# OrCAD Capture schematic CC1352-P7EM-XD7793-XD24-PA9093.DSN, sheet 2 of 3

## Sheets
2 CC1352-P7EM-XD7793-XD24-PA9093: size A3
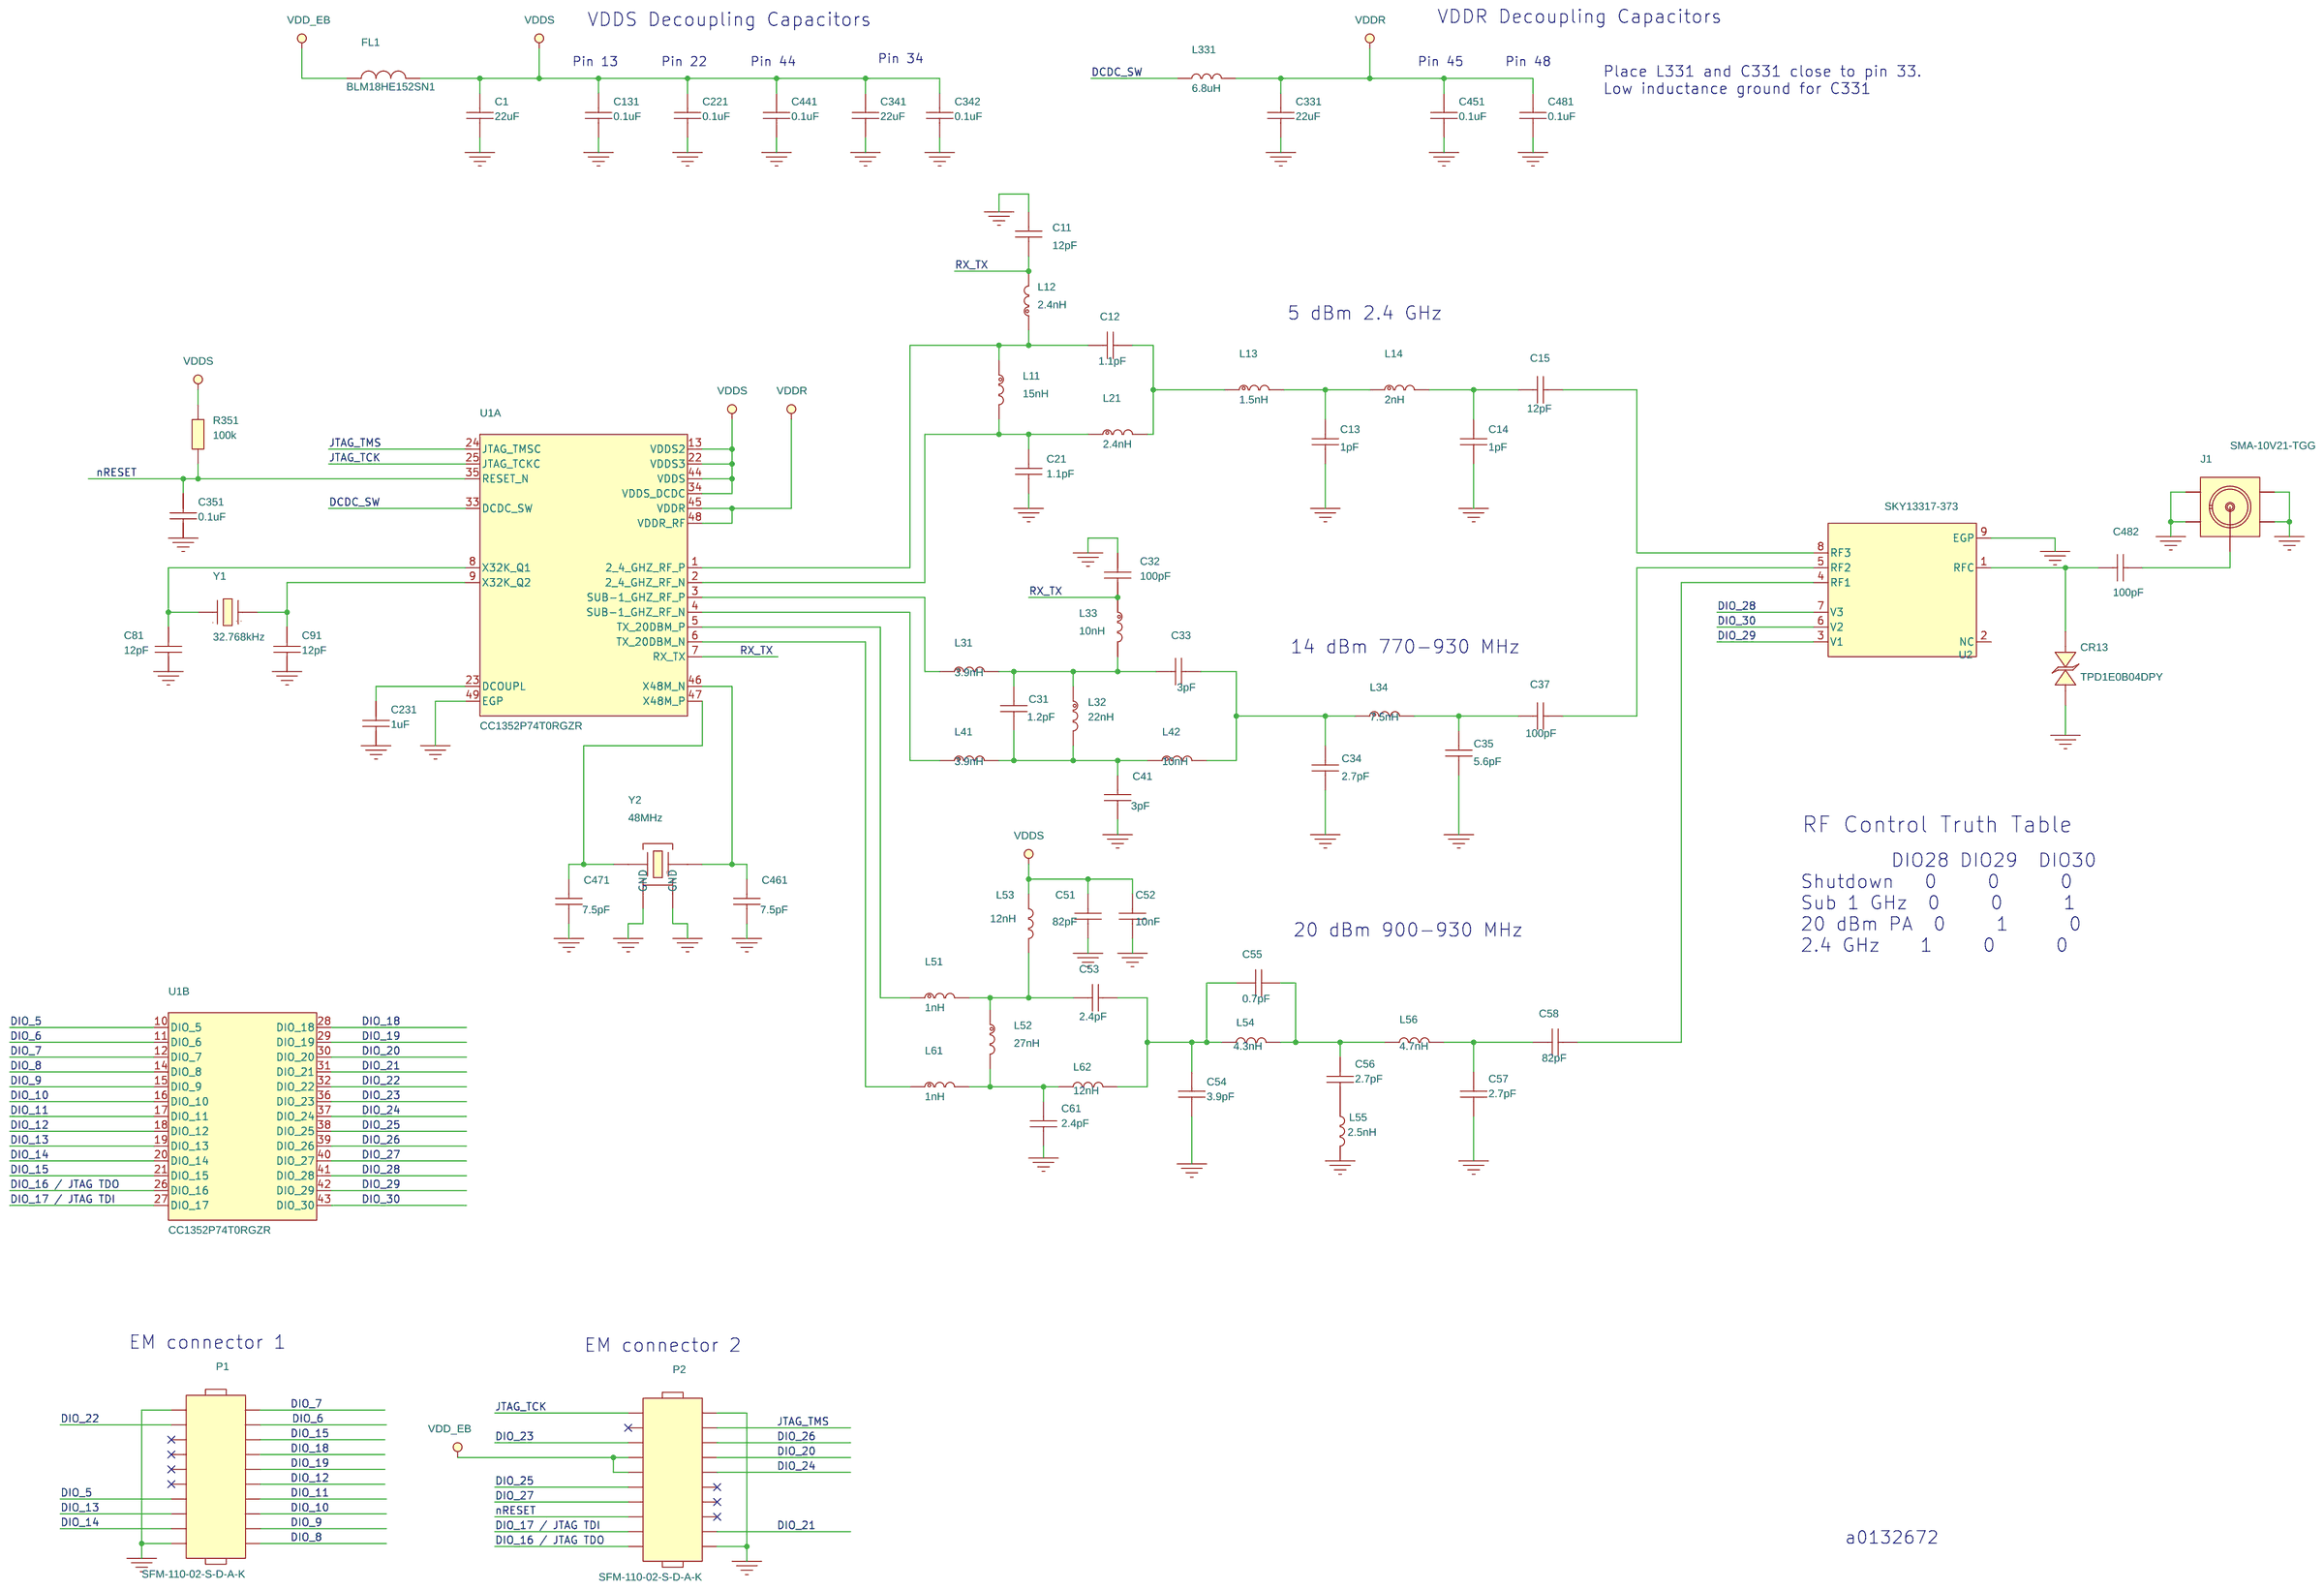
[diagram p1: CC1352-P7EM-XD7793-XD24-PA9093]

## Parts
C1  22uF  [CAPC1608X100A2N]
C11  12pF  [CAPC1005X60B2N]
C12  1.1pF  [CAPC1005X60B2N]
C13  1pF  [CAPC1005X60B2N]
C14  1pF  [CAPC1005X60B2N]
C15  12pF  [CAPC1005X60B2N]
C21  1.1pF  [CAPC1005X60B2N]
C31  1.2pF  [CAPC1005X60B2N]
C32  100pF  [CAPC1005X60B2N]
C33  3pF  [CAPC1005X60B2N]
C34  2.7pF  [CAPC1005X60B2N]
C35  5.6pF  [CAPC1005X60B2N]
C37  100pF  [CAPC1005X60B2N]
C41  3pF  [CAPC1005X60B2N]
C51  82pF  [CAPC1005X60B2N]
C52  10nF  [CAPC1005X60B2N]
C53  2.4pF  [CAPC1005X60B2N]
C54  3.9pF  [CAPC1005X60B2N]
C55  0.7pF  [CAPC1005X60B2N]
C56  2.7pF  [CAPC1005X60B2N]
C57  2.7pF  [CAPC1005X60B2N]
C58  82pF  [CAPC1005X60B2N]
C61  2.4pF  [CAPC1005X60B2N]
C81  12pF  [CAPC1005X60B2N]
C91  12pF  [CAPC1005X60B2N]
C131  0.1uF  [CAPC1005X60B2N]
C221  0.1uF  [CAPC1005X60B2N]
C231  1uF  [CAPC1005X60B2N]
C331  22uF  [CAPC1608X100A2N]
C341  22uF  [CAPC1608X100A2N]
C342  0.1uF  [CAPC1005X60B2N]
C351  0.1uF  [CAPC1005X60B2N]
C441  0.1uF  [CAPC1005X60B2N]
C451  0.1uF  [CAPC1005X60B2N]
C461  7.5pF  [CAPC1005X60B2N]
C471  7.5pF  [CAPC1005X60B2N]
C481  0.1uF  [CAPC1005X60B2N]
C482  100pF  [CAPC1005X60B2N]
CR13  TPD1E0B04DPY  [SON65P100X60X45-2A2N]
FL1  BLM18HE152SN1  [FIL_BLM18HE152SN1DN]
J1  SMA-10V21-TGG  [HUSTSAN_SMA10V21TGGAN]
L11  15nH  [INDC1005X60D2N]
L12  2.4nH  [INDC1005X60D2N]
L13  1.5nH  [INDC1005X60D2N]
L14  2nH  [INDC1005X60D2N]
L21  2.4nH  [INDC1005X60D2N]
L31  3.9nH  [INDC1005X60D2N]
L32  22nH  [INDC1005X60D2N]
L33  10nH  [INDC1005X60D2N]
L34  7.5nH  [INDC1005X60D2N]
L41  3.9nH  [INDC1005X60D2N]
L42  10nH  [INDC1005X60D2N]
L51  1nH  [INDC1005X60D2N]
L52  27nH  [INDC1005X60D2N]
L53  12nH  [INDC1005X60B2N]
L54  4.3nH  [INDC1005X60B2N]
L55  2.5nH  [INDC1005X60B2N]
L56  4.7nH  [INDC1005X60B2N]
L61  1nH  [INDC1005X60D2N]
L62  12nH  [INDC1005X60B2N]
L331  6.8uH  [INDC2012X150A2N]
P1  SFM-110-02-S-D-A-K  [SAMTEC_SFM11002AN]
P2  SFM-110-02-S-D-A-K  [SAMTEC_SFM11002AN]
R351  100k  [RESC1005X40B2N]
U1  CC1352P74T0RGZR  [QFNFC50P700X700X100-49A2N]  (sections A,B)
U2  SKY13317-373  [SON40P150X150X50-9A2N]
Y1  32.768kHz  [XTAL_TZ1166C_A2N]
Y2  48MHz  [OSCCC200X160X50-4A2N]

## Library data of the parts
C1 C331 C341 = CAPACITOR: CAPACITOR, CERAMIC X6S, 22uF, 6.3V, -20%/+20%, -55DEGC/+105DEGC, 0603, SMD; ALT_SYMBOLS: CAPC1608X100A2L,CAPC1608X100A2M; Additional Datasheet URL: https://search.murata.co.jp/Ceramy/image/img/A01X/G101/ENG/GRM188C80J226ME15-02A.pdf; AutoDoc File: https://notefied-dynamic-precision.com/DB/Apps/Desktop/Item/Object.aspx?id=104385; BU Name: DYNAMIC PRECISION GDANSK; Budget Currency: EUR; Budget Price: 0.062; Budgetary Price: 0.07648 USD; Client Status: UNDER_REVIEW; Datasheet URL: https://www.murata.com/-/media/webrenewal/support/library/catalog/products/capacitor/mlcc/c02e.ashx; Datasheet URL 1: http://psearch.murata.com/capacitor/product/GRM188R60J226MEA0%23.pdf; Datasheet URL 2: http://search.murata.co.jp/Ceramy/image/img/w_hinm/L0005E.pdf; Definied Quality: INDUSTRIAL; Dielectric Type: X6S; Esd Level: N/A; Lead Time: 15; LifeCycle Status: ACTIVE; MPN: GRM188R60J226MEA0D; MPN Status: ACTIVE; Manufacturer: MURATA; Mass: 0.0091g; Max Oper Temp: +85DEGC; Max Tol: +20%; Maximum Operating Temperature: +105DEGC; Maximum Tolerance: +20%; Min Oper Temp: -55DEGC; Min Tol: -20%; Minimum Operating Temperature: -55DEGC; Minimum Tolerance: -20%; Mounting Type: SMD; NOTE Status: PREFERRED; NOTEfied URL: https://notefied-dynamic-precision.com/NOTEfiedWebInterface/part/show?partNumber=02-09737; PCB Package: 0603; Packing Size: 4000; Packing Type: Tape & Reel; Part Number: 02-09737; Part Type: Capacitor|CERAMIC|0603|STANDARD; REACH/SVHC Compliance: Compliant; REACH/SVHC Details: SVHC List Version Jan 16, 2020; REACH/SVHC Source: REACH Declaration; REACH/SVHC Status: Unaffected; REACH/SVHC_COMPLIANCE: COMPLIANT; REACH/SVHC_DETAILS: SVHC LIST VERSION Dec 17, 2015; REACH/SVHC_SOURCE: REACH DECLARATION; REACH/SVHC_STATUS: UNAFFECTED; ROHS: Compliant; Rated Current: N/A; Rated Voltage: 6.3V; Revision: R001; RoHS Status: ROHS_COMPLIANT; Rtd Voltage: 6.3V; Status: Released; Texas Part Status: Under Review; Type: Capacitor; Vendor: MURATA; Vendor Part Number: GRM188C80J226ME15D; Vendor Part Status: Active; WEIGHT: 0.0091g
C11 C15 = CAPACITOR: CAPACITOR, CERAMIC C0G/NP0, 12pF, 50V, -5%/+5%, -55DEGC/+125DEGC, 0402, SMD; Additional Datasheet URL: https://search.murata.co.jp/Ceramy/image/img/A01X/G101/ENG/GJM1555C1H120JB01-01.pdf; AutoDoc File: https://notefied-dynamic-precision.com/DB/Apps/Desktop/Item/Object.aspx?id=113345; BU Name: TEXAS INSTRUMENTS NORWAY; Budget Currency: EUR; Budget Price: 0.007; Datasheet URL: https://www.murata.com/-/media/webrenewal/support/library/catalog/products/capacitor/mlcc/c02e.ashx; Datasheet URL 1: http://psearch.murata.com/capacitor/product/GRM1555C1H120JA01%23.pdf; Datasheet URL 2: http://search.murata.co.jp/Ceramy/image/img/w_hinm/L0005E.pdf; Dielectric Type: C0G/NP0; Mass: 0.0016g; Max Oper Temp: +125DEGC; Max Tol: +5%; Maximum Operating Temperature: +125DEGC; Maximum Tolerance: +5%; Min Oper Temp: -55DEGC; Min Tol: -5%; Minimum Operating Temperature: -55DEGC; Minimum Tolerance: -5%; Mounting Type: SMD; NOTEfied URL: https://notefied-dynamic-precision.com/NOTEfiedWebInterface/part/show?partNumber=02-09704; PCB Package: 0402; Packing Size: 10000; Packing Type: Tape & Reel; Part Number: 02-09704; Part Type: Capacitor|CERAMIC|0402|STANDARD; REACH/SVHC Compliance: Compliant; REACH/SVHC Details: SVHC List Version Jan 16, 2020; REACH/SVHC Source: REACH Declaration; REACH/SVHC Status: Unaffected; REACH/SVHC_COMPLIANCE: COMPLIANT; REACH/SVHC_DETAILS: SVHC LIST VERSION Dec 17, 2015; REACH/SVHC_SOURCE: REACH DECLARATION; REACH/SVHC_STATUS: UNAFFECTED; ROHS: Compliant; Rated Voltage: 50V; Revision: R002; RoHS Status: ROHS_COMPLIANT; Rtd Voltage: 50V; Status: Released; Texas Part Status: Under Review; Type: Capacitor; Vendor: MURATA; Vendor Part Number: GJM1555C1H120JB01D; Vendor Part Status: Active; Weight: 0.0016g
C12 C21 = CAPACITOR: CAPACITOR, CERAMIC C0G/NP0, 1.1pF, 50V, -0.1pF/+0.1pF, -55DEGC/+125DEGC, 0402, SMD; Additional Datasheet URL: https://search.murata.co.jp/Ceramy/image/img/A01X/G101/ENG/GJM1555C1H1R1BB01-01.pdf; AutoDoc File: https://notefied-dynamic-precision.com/DB/Apps/Desktop/Item/Object.aspx?id=116030; BU Name: TEXAS INSTRUMENTS NORWAY; Budget Currency: EUR; Budget Price: 0.011; Client Status: UNDER_REVIEW; Datasheet URL: https://www.murata.com/-/media/webrenewal/support/library/catalog/products/capacitor/mlcc/c02e.ashx; Datasheet URL 1: http://psearch.murata.com/capacitor/product/GRM1555C1H1R1BA01%23.pdf; Datasheet URL 2: http://search.murata.co.jp/Ceramy/image/img/w_hinm/L0005E.pdf; Dielectric Type: C0G/NP0; Mass: 0.0016g; Max Oper Temp: +125DEGC; Max Tol: +0.1pF; Maximum Operating Temperature: +125DEGC; Maximum Tolerance: +0.1pF; Min Oper Temp: -55DEGC; Min Tol: -0.1pF; Minimum Operating Temperature: -55DEGC; Minimum Tolerance: -0.1pF; Mounting Type: SMD; NOTEfied URL: https://notefied-dynamic-precision.com/NOTEfiedWebInterface/part/show?partNumber=02-09708; PCB Package: 0402; Packing Size: 10000; Packing Type: Tape & Reel; Part Number: 02-09708; Part Type: Capacitor|CERAMIC|0402|STANDARD; REACH/SVHC Compliance: Compliant; REACH/SVHC Details: SVHC List Version Jan 16, 2020; REACH/SVHC Source: REACH Declaration; REACH/SVHC Status: Unaffected; REACH/SVHC_COMPLIANCE: COMPLIANT; REACH/SVHC_DETAILS: SVHC LIST VERSION Jun 20, 2016; REACH/SVHC_SOURCE: REACH DECLARATION; REACH/SVHC_STATUS: UNAFFECTED; ROHS: Compliant; Rated Voltage: 50V; Revision: R002; RoHS Status: ROHS_COMPLIANT; Rtd Voltage: 50V; Status: Released; Texas Part Status: Under Review; Type: Capacitor; Vendor: MURATA; Vendor Part Number: GJM1555C1H1R1BB01D; Vendor Part Status: Active; Weight: 0.0016g
C13 C14 = CAPACITOR: CAPACITOR, CERAMIC C0G/NP0, 1pF, 50V, -0.1pF/+0.1pF, -55DEGC/+125DEGC, 0402, SMD; Additional Datasheet URL: https://search.murata.co.jp/Ceramy/image/img/A01X/G101/ENG/GJM1555C1H1R0BB01-01.pdf; AutoDoc File: https://notefied-dynamic-precision.com/DB/Apps/Desktop/Item/Object.aspx?id=116031; BU Name: TEXAS INSTRUMENTS NORWAY; Budget Currency: EUR; Budget Price: 0.011; Client Status: UNDER_REVIEW; Datasheet URL: https://www.murata.com/-/media/webrenewal/support/library/catalog/products/capacitor/mlcc/c02e.ashx; Datasheet URL 1: http://psearch.murata.com/capacitor/product/GRM1555C1H1R0BA01%23.pdf; Datasheet URL 2: http://search.murata.co.jp/Ceramy/image/img/w_hinm/L0005E.pdf; Dielectric Type: C0G/NP0; Mass: 0.0016g; Max Oper Temp: +125DEGC; Max Tol: +0.1pF; Maximum Operating Temperature: +125DEGC; Maximum Tolerance: +0.1pF; Min Oper Temp: -55DEGC; Min Tol: -0.1pF; Minimum Operating Temperature: -55DEGC; Minimum Tolerance: -0.1pF; Mounting Type: SMD; NOTEfied URL: https://notefied-dynamic-precision.com/NOTEfiedWebInterface/part/show?partNumber=02-09705; PCB Package: 0402; Packing Size: 10000; Packing Type: Tape & Reel; Part Number: 02-09705; Part Type: Capacitor|CERAMIC|0402|STANDARD; REACH/SVHC Compliance: Compliant; REACH/SVHC Details: SVHC List Version Jan 16, 2020; REACH/SVHC Source: REACH Declaration; REACH/SVHC Status: Unaffected; REACH/SVHC_COMPLIANCE: COMPLIANT; REACH/SVHC_DETAILS: SVHC LIST VERSION Dec 17, 2015; REACH/SVHC_SOURCE: REACH DECLARATION; REACH/SVHC_STATUS: UNAFFECTED; ROHS: Compliant; Rated Voltage: 50V; Revision: R002; RoHS Status: ROHS_COMPLIANT; Rtd Voltage: 50V; Status: Released; Texas Part Status: Under Review; Type: Capacitor; Vendor: MURATA; Vendor Part Number: GJM1555C1H1R0BB01D; Vendor Part Status: Active; Weight: 0.0016g
C31 = CAPACITOR: CAPACITOR, CERAMIC C0G/NP0, 1.2pF, 50V, -0.1pF/+0.1pF, -55DEGC/+125DEGC, 0402, SMD; Additional Datasheet URL: https://search.murata.co.jp/Ceramy/image/img/A01X/G101/ENG/GJM1555C1H1R2BB01-01.pdf; Datasheet URL: https://www.murata.com/-/media/webrenewal/support/library/catalog/products/capacitor/mlcc/c02e.ashx; Dielectric Type: C0G/NP0; Mass: 0.0016g; Maximum Operating Temperature: +125DEGC; Maximum Tolerance: +0.1pF; Minimum Operating Temperature: -55DEGC; Minimum Tolerance: -0.1pF; Mounting Type: SMD; NOTEfied URL: https://notefied-dynamic-precision.com/NOTEfiedWebInterface/part/show?partNumber=02-09709; PCB Package: 0402; Packing Size: 10000; Packing Type: Tape & Reel; Part Number: 02-09709; Part Type: Capacitor|CERAMIC|0402|STANDARD; REACH/SVHC Compliance: Compliant; REACH/SVHC Details: SVHC List Version Jan 16, 2020; REACH/SVHC Source: REACH Declaration; REACH/SVHC Status: Unaffected; ROHS: Compliant; Rated Voltage: 50V; Revision: R002; Status: Released; Texas Part Status: Under Review; Type: Capacitor; Vendor: MURATA; Vendor Part Number: GJM1555C1H1R2BB01D; Vendor Part Status: Active
C32 C37 = CAPACITOR: CAPACITOR, CERAMIC C0G/NP0, 100pF, 50V, -5%/+5%, -55DEGC/+125DEGC, 0402, SMD; Additional Datasheet URL: https://search.murata.co.jp/Ceramy/image/img/A01X/G101/ENG/GRT1555C1H101JA02-01.pdf; AutoDoc File: https://notefied-dynamic-precision.com/DB/Apps/Desktop/Item/Object.aspx?id=113347; BU Name: TEXAS INSTRUMENTS NORWAY; Budget Currency: EUR; Budget Price: 0.004; Budgetary Price: 0.023 EUR; Datasheet URL: https://www.murata.com/-/media/webrenewal/support/library/catalog/products/capacitor/mlcc/c02e.ashx?la=en-gb; Datasheet URL 1: http://psearch.murata.com/capacitor/product/GRM1555C1H101JA01%23.pdf; Datasheet URL 2: http://search.murata.co.jp/Ceramy/image/img/w_hinm/L0005E.pdf; Definied Quality: INDUSTRIAL; Dielectric Type: C0G/NP0; Esd Level: N/A; Lead Time: 19; MPN: GRM1555C1H101JA01D; MPN Status: ACTIVE; MSL: 1; MTBF: N/A; MTBF Standard: N/A; Manufacturer: MURATA; Mass: 0.0016g; Max Oper Temp: +125DEGC; Max Tol: +5%; Maximum Operating Temperature: +125DEGC; Maximum Tolerance: +5%; Min Oper Temp: -55DEGC; Min Tol: -5%; Minimum Operating Temperature: -55DEGC; Minimum Tolerance: -5%; Mounting Type: SMD; NOTE Status: PREFERRED; NOTEfied URL: https://notefied-dynamic-precision.com/NOTEfiedWebInterface/part/show?partNumber=02-09727; Old Footprint: CAPC1005X60N; PCB Package: 0402; Packing Size: 10000; Packing Type: Tape & Reel; Part Number: 02-09727; Part Type: Capacitor|CERAMIC|0402|STANDARD; REACH/SVHC Compliance: Compliant; REACH/SVHC Details: SVHC List Version Jan 16, 2020; REACH/SVHC Source: REACH Declaration; REACH/SVHC Status: Unaffected; REACH/SVHC_COMPLIANCE: COMPLIANT; REACH/SVHC_DETAILS: SVHC LIST VERSION Dec 17, 2015; REACH/SVHC_SOURCE: REACH DECLARATION; REACH/SVHC_STATUS: UNAFFECTED; ROHS: Compliant; Rated Voltage: 50V; Revision: R002; RoHS Status: ROHS_COMPLIANT; Rtd Voltage: 50V; Status: Released; Texas Part Status: Under Review; Type: Capacitor; Vendor: MURATA; Vendor Part Number: GRT1555C1H101JA02D; Vendor Part Status: Active; WEIGHT: 0.0016g
C33 C41 = CAPACITOR: CAPACITOR, CERAMIC C0G/NP0, 3pF, 50V, -0.25pF/+0.25pF, -55DEGC/+125DEGC, 0402, SMD; Additional Datasheet URL: https://search.murata.co.jp/Ceramy/image/img/A01X/G101/ENG/GJM1555C1H3R0CB01-01.pdf; Datasheet URL: https://www.murata.com/-/media/webrenewal/support/library/catalog/products/capacitor/mlcc/c02e.ashx; Dielectric Type: C0G/NP0; Mass: 0.0016g; Maximum Operating Temperature: +125DEGC; Maximum Tolerance: +0.25pF; Minimum Operating Temperature: -55DEGC; Minimum Tolerance: -0.25pF; Mounting Type: SMD; NOTEfied URL: https://notefied-dynamic-precision.com/NOTEfiedWebInterface/part/show?partNumber=02-09713; PCB Package: 0402; Packing Size: 10000; Packing Type: Tape & Reel; Part Number: 02-09713; Part Type: Capacitor|CERAMIC|0402|STANDARD; REACH/SVHC Compliance: Compliant; REACH/SVHC Details: SVHC List Version Jan 16, 2020; REACH/SVHC Source: REACH Declaration; REACH/SVHC Status: Unaffected; ROHS: Compliant; Rated Voltage: 50V; Revision: R002; Status: Released; Texas Part Status: Under Review; Type: Capacitor; Vendor: MURATA; Vendor Part Number: GJM1555C1H3R0CB01D; Vendor Part Status: Active
C34 = CAPACITOR: CAPACITOR, CERAMIC C0G/NP0, 2.7pF, 50V, -0.25pF/+0.25pF, -55DEGC/+125DEGC, 0402, SMD; Additional Datasheet URL: https://search.murata.co.jp/Ceramy/image/img/A01X/G101/ENG/GJM1555C1H2R7CB01-01.pdf; Datasheet URL: https://www.murata.com/-/media/webrenewal/support/library/catalog/products/capacitor/mlcc/c02e.ashx; Dielectric Type: C0G/NP0; Mass: 0.0016g; Maximum Operating Temperature: +125DEGC; Maximum Tolerance: +0.25pF; Minimum Operating Temperature: -55DEGC; Minimum Tolerance: -0.25pF; Mounting Type: SMD; NOTEfied URL: https://notefied-dynamic-precision.com/NOTEfiedWebInterface/part/show?partNumber=02-09712; PCB Package: 0402; Packing Size: 10000; Packing Type: Tape & Reel; Part Number: 02-09712; Part Type: Capacitor|CERAMIC|0402|STANDARD; REACH/SVHC Compliance: Compliant; REACH/SVHC Details: SVHC List Version Jan 16, 2020; REACH/SVHC Source: REACH Declaration; REACH/SVHC Status: Unaffected; ROHS: Compliant; Rated Voltage: 50V; Revision: R002; Status: Released; Texas Part Status: Under Review; Type: Capacitor; Vendor: MURATA; Vendor Part Number: GJM1555C1H2R7CB01D; Vendor Part Status: Active
C35 = CAPACITOR: CAPACITOR, CERAMIC C0G/NP0, 5.6pF, 50V, -0.25pF/+0.25pF, -55DEGC/+125DEGC, 0402, SMD; Additional Datasheet URL: https://search.murata.co.jp/Ceramy/image/img/A01X/G101/ENG/GJM1555C1H5R6CB01-01.pdf; Datasheet URL: https://www.murata.com/-/media/webrenewal/support/library/catalog/products/capacitor/mlcc/c02e.ashx; Dielectric Type: C0G/NP0; Mass: 0.0016g; Maximum Operating Temperature: +125DEGC; Maximum Tolerance: +0.25pF; Minimum Operating Temperature: -55DEGC; Minimum Tolerance: -0.25pF; Mounting Type: SMD; NOTEfied URL: https://notefied-dynamic-precision.com/NOTEfiedWebInterface/part/show?partNumber=02-09716; PCB Package: 0402; Packing Size: 10000; Packing Type: Tape & Reel; Part Number: 02-09716; Part Type: Capacitor|CERAMIC|0402|STANDARD; REACH/SVHC Compliance: Compliant; REACH/SVHC Details: SVHC List Version Jan 16, 2020; REACH/SVHC Source: REACH Declaration; REACH/SVHC Status: Unaffected; ROHS: Compliant; Rated Voltage: 50V; Revision: R002; Status: Released; Texas Part Status: Under Review; Type: Capacitor; Vendor: MURATA; Vendor Part Number: GJM1555C1H5R6CB01D; Vendor Part Status: Active
C51 C58 = CAPACITOR: CAPACITOR, CERAMIC C0G/NP0, 82pF, 50V, -5%/+5%, -55DEGC/+125DEGC, 0402, SMD; Additional Datasheet URL: https://search.murata.co.jp/Ceramy/image/img/A01X/G101/ENG/GRT1555C1H820JA02-01.pdf; AutoDoc File: https://notefied-dynamic-precision.com/DB/Apps/Desktop/Item/Object.aspx?id=115925; BU Name: TEXAS INSTRUMENTS NORWAY; Budget Currency: EUR; Budget Price: 0.007; Budgetary Price: 0.008 EUR; Client Status: UNDER_REVIEW; Country of Origin: Missing Info; Datasheet URL: https://www.murata.com/-/media/webrenewal/support/library/catalog/products/capacitor/mlcc/c02e.ashx?la=en-gb; Datasheet URL 1: http://psearch.murata.com/capacitor/product/GRM1555C1H820JA01%23.pdf; Datasheet URL 2: http://search.murata.co.jp/Ceramy/image/img/w_hinm/L0005E.pdf; Dielectric Type: C0G/NP0; Lead Time: 19; Mass: 0.0016g; Max Oper Temp: +125DEGC; Max Tol: +5%; Maximum Operating Temperature: +125DEGC; Maximum Tolerance: +5%; Min Oper Temp: -55DEGC; Min Tol: -5%; Minimum Operating Temperature: -55DEGC; Minimum Tolerance: -5%; Mounting Type: SMD; NOTEfied URL: https://notefied-dynamic-precision.com/NOTEfiedWebInterface/part/show?partNumber=02-09729; PCB Package: 0402; Packing Size: 10000; Packing Type: Tape & Reel; Part Number: 02-09729; Part Type: Capacitor|CERAMIC|0402|STANDARD; REACH/SVHC Compliance: Compliant; REACH/SVHC Details: SVHC List Version Jan 16, 2020; REACH/SVHC Source: REACH Declaration; REACH/SVHC Status: Unaffected; REACH/SVHC_COMPLIANCE: COMPLIANT; REACH/SVHC_DETAILS: SVHC LIST VERSION Jun 20, 2016; REACH/SVHC_SOURCE: REACH DECLARATION; REACH/SVHC_STATUS: UNAFFECTED; ROHS: Compliant; Rated Voltage: 50V; Revision: R002; RoHS Status: ROHS_COMPLIANT; Rtd Voltage: 50V; Status: Released; Texas Part Status: Under Review; Type: Capacitor; Vendor: MURATA; Vendor Part Number: GRT1555C1H820JA02D; Vendor Part Status: Active; Weight: 0.0016g
C52 = CAPACITOR: CAPACITOR, CERAMIC X7R, 10nF, 50V, -20%/+20%, -55DEGC/+125DEGC, 0402, SMD; Additional Datasheet URL: https://search.murata.co.jp/Ceramy/image/img/A01X/G101/ENG/GRM155R71H103MA88-01A.pdf; AutoDoc File: https://notefied-dynamic-precision.com/DB/Apps/Desktop/Item/Object.aspx?id=114570; BU Name: TEXAS INSTRUMENTS NORWAY; Budget Currency: EUR; Budget Price: 0.003; Client Status: UNDER_REVIEW; Datasheet URL: https://www.murata.com/-/media/webrenewal/support/library/catalog/products/capacitor/mlcc/c02e.ashx; Datasheet URL 1: http://psearch.murata.com/capacitor/product/GRM155R71E103KA01%23.pdf; Datasheet URL 2: http://search.murata.co.jp/Ceramy/image/img/w_hinm/L0005E.pdf; Dielectric Type: X7R; Mass: 0.0016g; Max Oper Temp: +125DEGC; Max Tol: +10%; Maximum Operating Temperature: +125DEGC; Maximum Tolerance: +20%; Min Oper Temp: -55DEGC; Min Tol: -10%; Minimum Operating Temperature: -55DEGC; Minimum Tolerance: -20%; Mounting Type: SMD; NOTEfied URL: https://notefied-dynamic-precision.com/NOTEfiedWebInterface/part/show?partNumber=02-09722; PCB Package: 0402; Packing Size: 10000; Packing Type: Tape & Reel; Part Number: 02-09722; Part Type: Capacitor|CERAMIC|0402|STANDARD; REACH/SVHC Compliance: Compliant; REACH/SVHC Details: SVHC List Version Jan 16, 2020; REACH/SVHC Source: REACH Declaration; REACH/SVHC Status: Unaffected; REACH/SVHC_COMPLIANCE: COMPLIANT; REACH/SVHC_DETAILS: SVHC LIST VERSION Jun 20, 2016; REACH/SVHC_SOURCE: REACH DECLARATION; REACH/SVHC_STATUS: UNAFFECTED; ROHS: Compliant; Rated Voltage: 50V; Revision: R002; RoHS Status: ROHS_COMPLIANT; Rtd Voltage: 25V; Status: Released; Texas Part Status: Under Review; Type: Capacitor; Vendor: MURATA; Vendor Part Number: GRM155R71H103MA88D; Vendor Part Status: Active; Weight: 0.0016g
C53 C61 = CAPACITOR: CAPACITOR, CERAMIC C0G/NP0, 2.4pF, 50V, -0.25pF/+0.25pF, -55DEGC/+125DEGC, 0402, SMD; Additional Datasheet URL: https://search.murata.co.jp/Ceramy/image/img/A01X/G101/ENG/GJM1555C1H2R4CB01-01.pdf; AutoDoc File: https://notefied-dynamic-precision.com/DB/Apps/Desktop/Item/Object.aspx?id=115907; BU Name: TEXAS INSTRUMENTS NORWAY; Budget Currency: EUR; Budget Price: 0.006; Client Status: UNDER_REVIEW; Datasheet URL: https://www.murata.com/-/media/webrenewal/support/library/catalog/products/capacitor/mlcc/c02e.ashx; Datasheet URL 1: http://psearch.murata.com/capacitor/product/GRM1555C1H2R4CA01%23.pdf; Datasheet URL 2: http://search.murata.co.jp/Ceramy/image/img/w_hinm/L0005E.pdf; Dielectric Type: C0G/NP0; Mass: 0.0016g; Max Oper Temp: +125DEGC; Max Tol: +0.25pF; Maximum Operating Temperature: +125DEGC; Maximum Tolerance: +0.25pF; Min Oper Temp: -55DEGC; Min Tol: -0.25pF; Minimum Operating Temperature: -55DEGC; Minimum Tolerance: -0.25pF; Mounting Type: SMD; NOTEfied URL: https://notefied-dynamic-precision.com/NOTEfiedWebInterface/part/show?partNumber=02-09711; PCB Package: 0402; Packing Size: 10000; Packing Type: Tape & Reel; Part Number: 02-09711; Part Type: Capacitor|CERAMIC|0402|STANDARD; REACH/SVHC Compliance: Compliant; REACH/SVHC Details: SVHC List Version Jan 16, 2020; REACH/SVHC Source: REACH Declaration; REACH/SVHC Status: Unaffected; ROHS: Compliant; Rated Voltage: 50V; Revision: R002; RoHS Status: ROHS_COMPLIANT; Rtd Voltage: 50V; Status: Released; Texas Part Status: Under Review; Type: Capacitor; Vendor: MURATA; Vendor Part Number: GJM1555C1H2R4CB01D; Vendor Part Status: Active; Weight: 0.0016g
C54 = CAPACITOR: CAPACITOR, CERAMIC C0G/NP0, 3.9pF, 50V, -0.25pF/+0.25pF, -55DEGC/+125DEGC, 0402, SMD; Additional Datasheet URL: https://search.murata.co.jp/Ceramy/image/img/A01X/G101/ENG/GJM1555C1H3R9CB01-01.pdf; AutoDoc File: https://notefied-dynamic-precision.com/DB/Apps/Desktop/Item/Object.aspx?id=115923; BU Name: TEXAS INSTRUMENTS NORWAY; Budget Currency: EUR; Budget Price: 0.007; Client Status: UNDER_REVIEW; Datasheet URL: https://www.murata.com/-/media/webrenewal/support/library/catalog/products/capacitor/mlcc/c02e.ashx; Datasheet URL 1: http://psearch.murata.com/capacitor/product/GRM1555C1H3R9CA01%23.pdf; Datasheet URL 2: http://search.murata.co.jp/Ceramy/image/img/w_hinm/L0005E.pdf; Dielectric Type: C0G/NP0; Mass: 0.0016g; Max Oper Temp: +125DEGC; Max Tol: +0.25pF; Maximum Operating Temperature: +125DEGC; Maximum Tolerance: +0.25pF; Min Oper Temp: -55DEGC; Min Tol: -0.25pF; Minimum Operating Temperature: -55DEGC; Minimum Tolerance: -0.25pF; Mounting Type: SMD; NOTEfied URL: https://notefied-dynamic-precision.com/NOTEfiedWebInterface/part/show?partNumber=02-09715; PCB Package: 0402; Packing Size: 10000; Packing Type: Tape & Reel; Part Number: 02-09715; Part Type: Capacitor|CERAMIC|0402|STANDARD; REACH/SVHC Compliance: Compliant; REACH/SVHC Details: SVHC List Version Jan 16, 2020; REACH/SVHC Source: REACH Declaration; REACH/SVHC Status: Unaffected; REACH/SVHC_COMPLIANCE: COMPLIANT; REACH/SVHC_DETAILS: SVHC LIST VERSION Jun 20, 2016; REACH/SVHC_SOURCE: REACH DECLARATION; REACH/SVHC_STATUS: UNAFFECTED; ROHS: Compliant; Rated Voltage: 50V; Revision: R002; RoHS Status: ROHS_COMPLIANT; Rtd Voltage: 50V; Status: Released; Texas Part Status: Under Review; Type: Capacitor; Vendor: MURATA; Vendor Part Number: GJM1555C1H3R9CB01D; Vendor Part Status: Active; Weight: 0.0016g
C55 = CAPACITOR: CAPACITOR, CERAMIC C0G/NP0, 0.7pF, 50V, -0.1pF/+0.1pF, -55DEGC/+125DEGC, 0402, SMD; Additional Datasheet URL: https://search.murata.co.jp/Ceramy/image/img/A01X/G101/ENG/GJM1555C1HR70BB01-01.pdf; AutoDoc File: https://notefied-dynamic-precision.com/DB/Apps/Desktop/Item/Object.aspx?id=116042; BU Name: TEXAS INSTRUMENTS NORWAY; Budget Currency: EUR; Budget Price: 0.017; Budgetary Price: 0.0274 USD; Client Status: UNDER_REVIEW; Country of Origin: Japan; Datasheet URL: https://www.murata.com/-/media/webrenewal/support/library/catalog/products/capacitor/mlcc/c02e.ashx; Datasheet URL 1: http://psearch.murata.com/capacitor/product/GRM1555C1HR70BA01%23.pdf; Datasheet URL 2: http://search.murata.co.jp/Ceramy/image/img/w_hinm/L0005E.pdf; Dielectric Type: C0G/NP0; Lead Time: 11; Mass: 0.0016g; Max Oper Temp: +125DEGC; Max Tol: +0.1pF; Maximum Operating Temperature: +125DEGC; Maximum Tolerance: +0.1pF; Min Oper Temp: -55DEGC; Min Tol: -0.1pF; Minimum Operating Temperature: -55DEGC; Minimum Tolerance: -0.1pF; Mounting Type: SMD; NOTEfied URL: https://notefied-dynamic-precision.com/NOTEfiedWebInterface/part/show?partNumber=02-06601; PCB Package: 0402; Packing Size: 10000; Packing Type: Tape & Reel; Part Number: 02-06601; Part Type: Capacitor|CERAMIC|0402|STANDARD; REACH/SVHC Compliance: Compliant; REACH/SVHC Details: SVHC List Version Jan 16, 2020; REACH/SVHC Source: REACH Declaration; REACH/SVHC Status: Unaffected; REACH/SVHC_COMPLIANCE: COMPLIANT; REACH/SVHC_DETAILS: SVHC LIST VERSION Jun 20, 2016; REACH/SVHC_SOURCE: REACH DECLARATION; REACH/SVHC_STATUS: UNAFFECTED; ROHS: Compliant; Rated Voltage: 50V; Revision: R009; RoHS Status: ROHS_COMPLIANT; Rtd Voltage: 50V; Status: Released; Texas Part Status: Under Review; Type: Capacitor; Vendor: MURATA; Vendor Part Number: GJM1555C1HR70BB01D; Vendor Part Status: Active; Weight: 0.0016g
C56 C57 = CAPACITOR: CAPACITOR, CERAMIC C0G/NP0, 2.7pF, 50V, -0.25pF/+0.25pF, -55DEGC/+125DEGC, 0402, SMD; Additional Datasheet URL: https://search.murata.co.jp/Ceramy/image/img/A01X/G101/ENG/GJM1555C1H2R7CB01-01.pdf; AutoDoc File: https://notefied-dynamic-precision.com/DB/Apps/Desktop/Item/Object.aspx?id=113356; BU Name: TEXAS INSTRUMENTS NORWAY; Budget Currency: EUR; Budget Price: 0.007; Datasheet URL: https://www.murata.com/-/media/webrenewal/support/library/catalog/products/capacitor/mlcc/c02e.ashx; Datasheet URL 1: http://psearch.murata.com/capacitor/product/GRM1555C1H2R7CA01%23.pdf; Datasheet URL 2: http://search.murata.co.jp/Ceramy/image/img/w_hinm/L0005E.pdf; Dielectric Type: C0G/NP0; Mass: 0.0016g; Max Oper Temp: +125DEGC; Max Tol: +0.25pF; Maximum Operating Temperature: +125DEGC; Maximum Tolerance: +0.25pF; Min Oper Temp: -55DEGC; Min Tol: -0.25pF; Minimum Operating Temperature: -55DEGC; Minimum Tolerance: -0.25pF; Mounting Type: SMD; NOTEfied URL: https://notefied-dynamic-precision.com/NOTEfiedWebInterface/part/show?partNumber=02-09712; PCB Package: 0402; Packing Size: 10000; Packing Type: Tape & Reel; Part Number: 02-09712; Part Type: Capacitor|CERAMIC|0402|STANDARD; REACH/SVHC Compliance: Compliant; REACH/SVHC Details: SVHC List Version Jan 16, 2020; REACH/SVHC Source: REACH Declaration; REACH/SVHC Status: Unaffected; REACH/SVHC_COMPLIANCE: COMPLIANT; REACH/SVHC_DETAILS: SVHC LIST VERSION Dec 17, 2015; REACH/SVHC_SOURCE: REACH DECLARATION; REACH/SVHC_STATUS: UNAFFECTED; ROHS: Compliant; Rated Voltage: 50V; Revision: R002; RoHS Status: ROHS_COMPLIANT; Rtd Voltage: 50V; Status: Released; Texas Part Status: Under Review; Type: Capacitor; Vendor: MURATA; Vendor Part Number: GJM1555C1H2R7CB01D; Vendor Part Status: Active; Weight: 0.0016g
C81 C91 = CAPACITOR: CAPACITOR, CERAMIC C0G/NP0, 12pF, 50V, -5%/+5%, -55DEGC/+125DEGC, 0402, SMD; Additional Datasheet URL: https://search.murata.co.jp/Ceramy/image/img/A01X/G101/ENG/GJM1555C1H120JB01-01.pdf; AutoDoc File: https://notefied-dynamic-precision.com/DB/Apps/Desktop/Item/Object.aspx?id=113345; BU Name: TEXAS INSTRUMENTS NORWAY; Budget Currency: EUR; Budget Price: 0.007; Datasheet URL: https://www.murata.com/-/media/webrenewal/support/library/catalog/products/capacitor/mlcc/c02e.ashx; Datasheet URL 1: http://psearch.murata.com/capacitor/product/GRM1555C1H120JA01%23.pdf; Datasheet URL 2: http://search.murata.co.jp/Ceramy/image/img/w_hinm/L0005E.pdf; Definied Quality: INDUSTRIAL; Dielectric Type: C0G/NP0; Esd Level: N/A; MPN: GRM1555C1H120JA01D; MPN Status: ACTIVE; MSL: 1; MTBF: N/A; MTBF Standard: N/A; Manufacturer: MURATA; Mass: 0.0016g; Max Oper Temp: +125DEGC; Max Tol: +5%; Maximum Operating Temperature: +125DEGC; Maximum Tolerance: +5%; Min Oper Temp: -55DEGC; Min Tol: -5%; Minimum Operating Temperature: -55DEGC; Minimum Tolerance: -5%; Mounting Type: SMD; NOTE Status: PREFERRED; NOTEfied URL: https://notefied-dynamic-precision.com/NOTEfiedWebInterface/part/show?partNumber=02-09704; Old Footprint: CAPC1005X60N; PCB Package: 0402; Packing Size: 10000; Packing Type: Tape & Reel; Part Number: 02-09704; Part Type: Capacitor|CERAMIC|0402|STANDARD; REACH/SVHC Compliance: Compliant; REACH/SVHC Details: SVHC List Version Jan 16, 2020; REACH/SVHC Source: REACH Declaration; REACH/SVHC Status: Unaffected; REACH/SVHC_COMPLIANCE: COMPLIANT; REACH/SVHC_DETAILS: SVHC LIST VERSION Dec 17, 2015; REACH/SVHC_SOURCE: REACH DECLARATION; REACH/SVHC_STATUS: UNAFFECTED; ROHS: Compliant; Rated Voltage: 50V; Revision: R002; RoHS Status: ROHS_COMPLIANT; Rtd Voltage: 50V; Status: Released; Texas Part Status: Under Review; Type: Capacitor; Vendor: MURATA; Vendor Part Number: GJM1555C1H120JB01D; Vendor Part Status: Active; WEIGHT: 0.0016g
C131 C221 C351 C441 C451 C481 = CAPACITOR: CAPACITOR, CERAMIC X7R, 0.1uF, 25V, -10%/+10%, -55DEGC/+125DEGC, 0402, SMD; Additional Datasheet URL: https://search.murata.co.jp/Ceramy/image/img/A01X/G101/ENG/GRM155R71E104KE14-01A.pdf; AutoDoc File: https://notefied-dynamic-precision.com/DB/Apps/Desktop/Item/Object.aspx?id=115293; BU Name: TEXAS INSTRUMENTS NORWAY; Client Status: UNDER_REVIEW; Datasheet URL: https://www.murata.com/~/media/webrenewal/support/library/catalog/products/capacitor/mlcc/c02e.ashx?la=en-gb; Datasheet URL 1: http://psearch.en.murata.com/capacitor/product/GRM155R71E104KE14%23.pdf; Datasheet URL 2: http://search.murata.co.jp/Ceramy/image/img/w_hinm/L0005E.pdf; Dielectric Type: X7R; LifeCycle Status: ACTIVE; MPN: GRM155R70J104KA01D; MPN Status: ACTIVE; Manufacturer: MURATA; Mass: 0.0016g; Max Oper Temp: +125DEGC; Max Tol: +10%; Maximum Operating Temperature: +125DEGC; Maximum Tolerance: +10%; Min Oper Temp: -55DEGC; Min Tol: -10%; Minimum Operating Temperature: -55DEGC; Minimum Tolerance: -10%; Mounting Type: SMD; NOTE Status: PREFERRED; NOTEfied URL: https://notefied-dynamic-precision.com/NOTEfiedWebInterface/part/show?partNumber=02-07861; Old Footprint: CAPC1005X60N,0402; PCB Package: 0402; Packing Size: 10000; Packing Type: Tape & Reel; Part Number: 02-07861; Part Type: Capacitor|CERAMIC|0402|STANDARD; REACH/SVHC Compliance: Compliant; REACH/SVHC Details: SVHC List Version Jul 7, 2017; REACH/SVHC Source: REACH Declaration; REACH/SVHC Status: Unaffected; REACH/SVHC_COMPLIANCE: COMPLIANT; REACH/SVHC_DETAILS: SVHC LIST VERSION Jun 20, 2016; REACH/SVHC_SOURCE: REACH DECLARATION; REACH/SVHC_STATUS: UNAFFECTED; ROHS: Compliant; Rated Voltage: 25V; Revision: R014; RoHS Status: ROHS_COMPLIANT; Rtd Voltage: 25V; Status: Released; Texas Part Status: Under Review; Type: Capacitor; Vendor: MURATA; Vendor Part Number: GRM155R71E104KE14D; Vendor Part Status: NRND; WEIGHT: 0.0016g
C231 = CAPACITOR: CAPACITOR, CERAMIC X6S, 1uF, 16V, -10%/+10%, -55DEGC/+105DEGC, 0402, SMD; Additional Datasheet URL: https://search.murata.co.jp/Ceramy/image/img/A01X/G101/ENG/GRM155C81C105KE11-01A.pdf; AutoDoc File: https://notefied-dynamic-precision.com/DB/Apps/Desktop/Item/Object.aspx?id=115295; BU Name: TEXAS INSTRUMENTS NORWAY; Client Status: UNDER_REVIEW; Datasheet URL: https://www.murata.com/-/media/webrenewal/support/library/catalog/products/capacitor/mlcc/c02e.ashx; Datasheet URL 1: http://psearch.en.murata.com/capacitor/product/GRM155R61C105KA12%23.pdf; Datasheet URL 2: http://search.murata.co.jp/Ceramy/image/img/w_hinm/L0005E.pdf; Definied Quality: INDUSTRIAL; Dielectric Type: X6S; Esd Level: N/A; MPN: GRM155R61A105KE15D; MPN Status: ACTIVE; MSL: 1; MTBF: N/A; MTBF Standard: N/A; Manufacturer: MURATA; Mass: 0.0016g; Max Oper Temp: +85DEGC; Max Tol: +10%; Maximum Operating Temperature: +105DEGC; Maximum Tolerance: +10%; Min Oper Temp: -55DEGC; Min Tol: -10%; Minimum Operating Temperature: -55DEGC; Minimum Tolerance: -10%; Mounting Type: SMD; NOTE Status: PREFERRED; NOTEfied URL: https://notefied-dynamic-precision.com/NOTEfiedWebInterface/part/show?partNumber=02-09724; Old Footprint: CAPC1005X60N,0402; PCB Package: 0402; Packing Size: 10000; Packing Type: Tape & Reel; Part Number: 02-09724; Part Type: Capacitor|CERAMIC|0402|STANDARD; REACH/SVHC Compliance: Compliant; REACH/SVHC Details: SVHC List Version Jan 16, 2020; REACH/SVHC Source: REACH Declaration; REACH/SVHC Status: Unaffected; REACH/SVHC_COMPLIANCE: COMPLIANT; REACH/SVHC_DETAILS: SVHC LIST VERSION Jun 20, 2016; REACH/SVHC_SOURCE: REACH DECLARATION; REACH/SVHC_STATUS: UNAFFECTED; ROHS: Compliant; Rated Voltage: 16V; Revision: R002; RoHS Status: ROHS_COMPLIANT; Rtd Voltage: 16V; Status: Released; Texas Part Status: Under Review; Type: Capacitor; Vendor: MURATA; Vendor Part Number: GRM155C81C105KE11D; Vendor Part Status: Active; WEIGHT: 0.0016g
C342 = CAPACITOR: CAPACITOR, CERAMIC X7R, 0.1uF, 25V, -10%/+10%, -55DEGC/+125DEGC, 0402, SMD; Additional Datasheet URL: https://search.murata.co.jp/Ceramy/image/img/A01X/G101/ENG/GRM155R71E104KE14-01A.pdf; AutoDoc File: https://notefied-dynamic-precision.com/DB/Apps/Desktop/Item/Object.aspx?id=115293; BU Name: TEXAS INSTRUMENTS NORWAY; Cage Code: C0151; Client Status: UNDER_REVIEW; Datasheet URL: https://www.murata.com/~/media/webrenewal/support/library/catalog/products/capacitor/mlcc/c02e.ashx?la=en-gb; Datasheet URL 1: http://psearch.en.murata.com/capacitor/product/GRM155R71E104KE14%23.pdf; Datasheet URL 2: http://search.murata.co.jp/Ceramy/image/img/w_hinm/L0005E.pdf; Definied Quality: INDUSTRIAL; Dielectric Type: X7R; Esd Level: N/A; MPN: GRM188R71E104KA01D; MPN Status: NRND; MSL: 1; MTBF: N/A; MTBF Standard: N/A; Manufacturer: MURATA; Mass: 0.0016g; Max Oper Temp: +125DEGC; Max Tol: +10%; Maximum Operating Temperature: +125DEGC; Maximum Tolerance: +10%; Min Oper Temp: -55DEGC; Min Tol: -10%; Minimum Operating Temperature: -55DEGC; Minimum Tolerance: -10%; Mounting Type: SMD; NOTE Status: PREFERRED; NOTEfied URL: https://notefied-dynamic-precision.com/NOTEfiedWebInterface/part/show?partNumber=02-07861; Old Footprint: CAPC1608X90N,0603; PCB Package: 0402; Packing Size: 10000; Packing Type: Tape & Reel; Part Number: 02-07861; Part Type: Capacitor|CERAMIC|0402|STANDARD; REACH/SVHC Compliance: Compliant; REACH/SVHC Details: SVHC List Version Jul 7, 2017; REACH/SVHC Source: REACH Declaration; REACH/SVHC Status: Unaffected; REACH/SVHC_COMPLIANCE: COMPLIANT; REACH/SVHC_DETAILS: SVHC LIST VERSION Jun 20, 2016; REACH/SVHC_SOURCE: REACH DECLARATION; REACH/SVHC_STATUS: UNAFFECTED; ROHS: Compliant; Rated Voltage: 25V; Revision: R014; RoHS Status: ROHS_COMPLIANT; Rtd Voltage: 25V; Status: Released; Texas Part Status: Under Review; Type: Capacitor; Vendor: MURATA; Vendor Part Number: GRM155R71E104KE14D; Vendor Part Status: NRND; WEIGHT: 0.0016g
C461 C471 = CAPACITOR: CAPACITOR, CERAMIC C0G/NP0, 7.5pF, 50V, -0.25pF/+0.25pF, -55DEGC/+125DEGC, 0402, SMD; Additional Datasheet URL: https://search.murata.co.jp/Ceramy/image/img/A01X/G101/ENG/GJM1555C1H7R5CB01-01.pdf; Datasheet URL: https://www.murata.com/-/media/webrenewal/support/library/catalog/products/capacitor/mlcc/c02e.ashx; Dielectric Type: C0G/NP0; Mass: 0.0016g; Maximum Operating Temperature: +125DEGC; Maximum Tolerance: +0.25pF; Minimum Operating Temperature: -55DEGC; Minimum Tolerance: -0.25pF; Mounting Type: SMD; NOTEfied URL: https://notefied-dynamic-precision.com/NOTEfiedWebInterface/part/show?partNumber=02-09718; PCB Package: 0402; Packing Size: 10000; Packing Type: Tape & Reel; Part Number: 02-09718; Part Type: Capacitor|CERAMIC|0402|STANDARD; REACH/SVHC Compliance: Compliant; REACH/SVHC Details: SVHC List Version Jan 16, 2020; REACH/SVHC Source: REACH Declaration; REACH/SVHC Status: Unaffected; ROHS: Compliant; Rated Voltage: 50V; Revision: R002; Status: Released; Texas Part Status: Under Review; Type: Capacitor; Vendor: MURATA; Vendor Part Number: GJM1555C1H7R5CB01D; Vendor Part Status: Active
C482 = CAPACITOR: CAPACITOR, CERAMIC C0G/NP0, 100pF, 50V, -5%/+5%, -55DEGC/+125DEGC, 0402, SMD; Additional Datasheet URL: https://search.murata.co.jp/Ceramy/image/img/A01X/G101/ENG/GRT1555C1H101JA02-01.pdf; Budgetary Price: 0.023 EUR; Datasheet URL: https://www.murata.com/-/media/webrenewal/support/library/catalog/products/capacitor/mlcc/c02e.ashx?la=en-gb; Dielectric Type: C0G/NP0; Lead Time: 19; Mass: 0.0016g; Maximum Operating Temperature: +125DEGC; Maximum Tolerance: +5%; Minimum Operating Temperature: -55DEGC; Minimum Tolerance: -5%; Mounting Type: SMD; NOTEfied URL: https://notefied-dynamic-precision.com/NOTEfiedWebInterface/part/show?partNumber=02-09727; PCB Package: 0402; Packing Size: 10000; Packing Type: Tape & Reel; Part Number: 02-09727; Part Type: Capacitor|CERAMIC|0402|STANDARD; REACH/SVHC Compliance: Compliant; REACH/SVHC Details: SVHC List Version Jan 16, 2020; REACH/SVHC Source: REACH Declaration; REACH/SVHC Status: Unaffected; ROHS: Compliant; Rated Voltage: 50V; Revision: R002; Status: Released; Texas Part Status: Under Review; Type: Capacitor; Vendor: MURATA; Vendor Part Number: GRT1555C1H101JA02D; Vendor Part Status: Active
CR13 = DIODE_TVS_BIDIR_S: DIODE, PROTECTION, TVS, BID, 6.7V, 15W, -40DEGC/+125DEGC, X1SON2, SMD; Additional Datasheet URL: http://www.ti.com/litv/pdf/mpss034c; AutoDoc File: https://notefied-dynamic-precision.com/DB/Apps/Desktop/Item/Object.aspx?id=118028; BU Name: DYNAMIC PRECISION GDANSK; Budget Currency: USD; Budget Price: 0.08; Budgetary Price: 0.08 USD; Client Status: UNDER_REVIEW; Datasheet URL: http://www.ti.com/lit/ds/symlink/tpd1e0b04.pdf; Datasheet URL 1: http://www.ti.com/lit/ds/symlink/tpd1e0b04.pdf; Datasheet URL 2: http://www.ti.com/lit/ml/mpss034c/mpss034c.pdf; Lead Time: 8; Mass: 0.0031g; Max Oper Temp: +125DEGC; Maximum Operating Temperature: +125DEGC; Min Oper Temp: -40DEGC; Minimum Operating Temperature: -40DEGC; Mounting Type: SMD; NOTEfied URL: https://notefied-dynamic-precision.com/NOTEfiedWebInterface/part/show?partNumber=14-06704; PCB Package: SON2; Packing Size: 10000; Packing Type: Tape & Reel; Part Number: 14-06704; Part Type: Diode|PROTECTION; REACH/SVHC Compliance: Compliant; REACH/SVHC Details: SVHC List Version Jan 12, 2017; REACH/SVHC Source: REACH Declaration; REACH/SVHC Status: Unaffected; ROHS: Compliant; Rated Power: 15W; Rated Voltage: 6.7V; Revision: R015; RoHS Status: ROHS_COMPLIANT; Rtd Power: 15W; Rtd Voltage: 6.7V; Status: Released; Texas Part Status: Under Review; Type: Diode; Vendor: TEXAS INSTRUMENTS; Vendor Part Number: TPD1E0B04DPYR; Vendor Part Status: Active; Weight: 0.0031g
FL1 = FILTER_2PIN: FILTER, EMI, FERRITE BEAD, 1500@100MHz, -25%/+25%, -55DEGC/+125DEGC, 0603, SMD; ALT_SYMBOLS: FIL_BLM18HE152SN1DL,FIL_BLM18HE152SN1DM; Additional Datasheet URL: https://www.murata.com/en-eu/products/productdata/8796741599262/ENFA0004.pdf?1441769419000; AutoDoc File: https://notefied-dynamic-precision.com/DB/Apps/Desktop/Item/Object.aspx?id=85575; BU Name: DYNAMIC PRECISION GDANSK; Budget Currency: EUR; Budget Price: 0.065; Budgetary Price: 0.065 EUR; CLASS: IC; Client Status: UNDER_REVIEW; Country of Origin: Japan,Singapore,Thailand; Datasheet URL: https://www.murata.com/~/media/webrenewal/support/library/catalog/products/emc/emifil/c31e.ashx; Datasheet URL 1: http://search.murata.co.jp/Ceramy/image/img/PDF/ENG/L0110S0101BLM18H.pdf; Datasheet URL 2: http://search.murata.co.jp/Ceramy/image/img/w_hinm/L0110E.pdf; Frequency: 100MHz; Impedance: 1500; Inductance: N/A; Lead Time: 9; MPN: BLM18HE152SN1D; MPN Status: ACTIVE; Manufacturer: MURATA; Mass: 0.006g; Max Oper Temp: +125DEGC; Max Tol: +25%; Maximum Operating Temperature: +125DEGC; Maximum Tolerance: +25%; Min Oper Temp: -55DEGC; Min Tol: -25%; Minimum Operating Temperature: -55DEGC; Minimum Tolerance: -25%; Mounting Type: SMD; NOTE Status: PREFERRED; NOTEfied URL: https://notefied-dynamic-precision.com/NOTEfiedWebInterface/part/show?partNumber=04-00470; PCB Package: 0603; Packing Size: 4000; Packing Type: Tape & Reel; Part Number: 04-00470; Part Type: Filter|EMI|FERRITE BEAD|0603; REACH/SVHC Compliance: Compliant; REACH/SVHC Details: SVHC List Version Jul 7, 2017; REACH/SVHC Source: REACH Declaration; REACH/SVHC Status: Unaffected; REACH/SVHC_COMPLIANCE: COMPLIANT; REACH/SVHC_DETAILS: SVHC LIST VERSION Dec 17, 2015; REACH/SVHC_SOURCE: REACH DECLARATION; REACH/SVHC_STATUS: UNAFFECTED; ROHS: Compliant; Rated Current: 0.5A; Rated Voltage: N/A; Revision: R015; RoHS Status: ROHS_COMPLIANT; Rtd Current: 0.5A; Rtd Voltage: N/A; Status: Released; Texas Part Status: Under Review; Type: Filter; Vendor: MURATA; Vendor Part Number: BLM18HE152SN1D; Vendor Part Status: Active; WEIGHT: 0.006g
J1 = CONN_COAX_1+4: CONNECTOR, COAX, RF, FEMALE, STRAIGHT, 1 PIN, SMD; ALT_SYMBOLS: HUSTSAN_SMA10V21TGGL,HUSTSAN_SMA10V21TGGM; Additional Datasheet URL: http://www.hustsan.com.tw/cgi-bin/productfn/pdt_detail_lst.pl?ProdID=143; AutoDoc File: https://notefied-dynamic-precision.com/DB/Apps/Desktop/Item/Object.aspx?id=84956; BU Name: DYNAMIC PRECISION GDANSK; Budget Currency: N/A; Budget Price: N/A; CLASS: IO; Client Status: UNDER_REVIEW; Country of Origin: Taiwan; Datasheet URL: http://www.hustsan.com.tw/uploaddir/product/SMA-10V21.pdf; Datasheet URL 1: http://www.hustsan.com.tw/uploaddir/product/SMA-10V21.pdf; Datasheet URL 2: http://www.hustsan.com.tw/cgi-bin/productfn/pdt_detail_lst.pl?ProdID=143; FPLIST: HUSTSAN_SMA10V21TGGAN,HUSTSAN_SMA10V21TGGN; MPN Status: ACTIVE; MSL: N/A; Manufacturer: HUS-TSAN; Mass: N/A; Mounting Type: SMD; NOTE Status: PREFERRED; NOTEfied URL: https://notefied-dynamic-precision.com/NOTEfiedWebInterface/part/show?partNumber=06-02188; No Of Pos: 1; Number of Positions: 1; Old Footprint: HUSTSAN_SMA10V21TGGAN,HUSTSAN_SMA10V21TGGN; Packing Size: 350; Packing Type: Tape & Reel; Part Number: 06-02188; Part Type: Connector|COAX|RF; REACH/SVHC Compliance: Compliant; REACH/SVHC Details: SVHC List Version Jun 20, 2016; REACH/SVHC Source: REACH Declaration; REACH/SVHC Status: Unaffected; ROHS: Compliant; Revision: R014; RoHS Status: ROHS_COMPLIANT; Status: Released; Texas Part Status: Under Review; Type: Connector; Vendor: HUS-TSAN; Vendor Part Status: Active; WEIGHT: N/A
L11 = INDUCTOR_HOR_1_2: INDUCTOR, RF, CHIP, NON-MAGNETIC CORE, 15nH, -5%/+5%, 0.3A, -55DEGC/+125DEGC, 0402, SMD; ALT_SYMBOLS: INDC1005X60C2L,INDC1005X60C2M; Additional Datasheet URL: https://search.murata.co.jp/Ceramy/image/img/P02/JELF243B-0010.pdf; Budgetary Price: 0.03 EUR; Country of Origin: Japan,Singapore; Datasheet URL: https://www.murata.com/~/media/webrenewal/support/library/catalog/products/inductor/chip/o05e.ashx?la=en-gb; Frequency: 2.5GHz; Lead Time: 9; Mass: 0.001g; Maximum Operating Temperature: +125DEGC; Maximum Tolerance: +5%; Minimum Operating Temperature: -55DEGC; Minimum Tolerance: -5%; Mounting Type: SMD; NOTEfied URL: https://notefied-dynamic-precision.com/NOTEfiedWebInterface/part/show?partNumber=03-06637; PCB Package: 0402; Packing Size: 10000; Packing Type: Tape & Reel; Part Number: 03-06637; Part Type: Inductor|RF|CHIP|0402; REACH/SVHC Compliance: Compliant; REACH/SVHC Details: SVHC List Version Jul 7, 2017; REACH/SVHC Source: REACH Declaration; REACH/SVHC Status: Unaffected; ROHS: Compliant; Resistance: 0.32; Revision: R019; Status: Released; Texas Part Status: Under Review; Type: Inductor; Vendor: MURATA; Vendor Part Number: LQG15HS15NJ02D; Vendor Part Status: Active
L12 L21 = INDUCTOR_HOR_1_2: INDUCTOR, RF, CHIP, NON-MAGNETIC CORE, 2.4nH, -0.3nH/+0.3nH, 0.3A, -55DEGC/+125DEGC, 0402, SMD; Additional Datasheet URL: https://search.murata.co.jp/Ceramy/image/img/P02/JELF243B-0010.pdf; Budgetary Price: 0.031 EUR; Country of Origin: Japan,Singapore; Datasheet URL: https://www.murata.com/~/media/webrenewal/support/library/catalog/products/inductor/chip/o05e.ashx?la=en-gb; Exclusive for Customers: TEXAS INSTRUMENTS NORWAY; Frequency: 6GHz; Lead Time: 9; Mass: 0.001g; Maximum Operating Temperature: +125DEGC; Maximum Tolerance: +0.3nH; Minimum Operating Temperature: -55DEGC; Minimum Tolerance: -0.3nH; Mounting Type: SMD; NOTEfied URL: https://notefied-dynamic-precision.com/NOTEfiedWebInterface/part/show?partNumber=03-07526; Notes: Standard item: Duplicate Reason: custom footprint for TEXAS INSTRUMENTS NORWAY.; PCB Package: 0402; Packing Size: 10000; Packing Type: Tape & Reel; Part Number: 03-07526; Part Type: Inductor|RF|CHIP|0402; REACH/SVHC Compliance: Compliant; REACH/SVHC Details: SVHC List Version Jul 7, 2017; REACH/SVHC Source: REACH Declaration; REACH/SVHC Status: Unaffected; ROHS: Compliant; Revision: R019; Status: Released; Texas Part Status: Under Review; Type: Inductor; Vendor: MURATA; Vendor Part Number: LQG15HS2N4S02D; Vendor Part Status: Active
L13 = INDUCTOR_HOR_1_2: INDUCTOR, RF, CHIP, NON-MAGNETIC CORE, 1.5nH, -0.3nH/+0.3nH, 0.3A, -55DEGC/+125DEGC, 0402, SMD; Additional Datasheet URL: https://search.murata.co.jp/Ceramy/image/img/P02/JELF243B-0010.pdf; Budgetary Price: 0.031 EUR; Country of Origin: Japan,Singapore; Datasheet URL: https://www.murata.com/~/media/webrenewal/support/library/catalog/products/inductor/chip/o05e.ashx?la=en-gb; Exclusive for Customers: TEXAS INSTRUMENTS NORWAY; Frequency: 6GHz; Lead Time: 10; Mass: 0.001g; Maximum Operating Temperature: +125DEGC; Maximum Tolerance: +0.3nH; Minimum Operating Temperature: -55DEGC; Minimum Tolerance: -0.3nH; Mounting Type: SMD; NOTEfied URL: https://notefied-dynamic-precision.com/NOTEfiedWebInterface/part/show?partNumber=03-07531; Notes: Standard item: Duplicate Reason: custom footprint for TEXAS INSTRUMENTS NORWAY.; PCB Package: 0402; Packing Size: 10000; Packing Type: Tape & Reel; Part Number: 03-07531; Part Type: Inductor|RF|CHIP|0402; REACH/SVHC Compliance: Compliant; REACH/SVHC Details: SVHC List Version Jul 7, 2017; REACH/SVHC Source: REACH Declaration; REACH/SVHC Status: Unaffected; ROHS: Compliant; Resistance: 0.1; Revision: R018; Status: Released; Texas Part Status: Under Review; Type: Inductor; Vendor: MURATA; Vendor Part Number: LQG15HS1N5S02D; Vendor Part Status: Active
L14 = INDUCTOR_HOR_1_2: INDUCTOR, RF, CHIP, NON-MAGNETIC CORE, 2nH, -0.3nH/+0.3nH, 0.3A, -55DEGC/+125DEGC, 0402, SMD; Additional Datasheet URL: https://search.murata.co.jp/Ceramy/image/img/P02/JELF243B-0010.pdf; Budgetary Price: 0.031 EUR; Country of Origin: Japan,Singapore; Datasheet URL: https://www.murata.com/~/media/webrenewal/support/library/catalog/products/inductor/chip/o05e.ashx?la=en-gb; Exclusive for Customers: TEXAS INSTRUMENTS NORWAY; Frequency: 6GHz; Lead Time: 10; Mass: 0.001g; Maximum Operating Temperature: +125DEGC; Maximum Tolerance: +0.3nH; Minimum Operating Temperature: -55DEGC; Minimum Tolerance: -0.3nH; Mounting Type: SMD; NOTEfied URL: https://notefied-dynamic-precision.com/NOTEfiedWebInterface/part/show?partNumber=03-07527; Notes: Standard item: Duplicate Reason: custom footprint for TEXAS INSTRUMENTS NORWAY.; PCB Package: 0402; Packing Size: 10000; Packing Type: Tape & Reel; Part Number: 03-07527; Part Type: Inductor|RF|CHIP|0402; REACH/SVHC Compliance: Compliant; REACH/SVHC Details: SVHC List Version Jul 7, 2017; REACH/SVHC Source: REACH Declaration; REACH/SVHC Status: Unaffected; ROHS: Compliant; Revision: R018; Status: Released; Texas Part Status: Under Review; Type: Inductor; Vendor: MURATA; Vendor Part Number: LQG15HS2N0S02D; Vendor Part Status: Active
L31 L41 = INDUCTOR_HOR_1_2: INDUCTOR, RF, CHIP, NON-MAGNETIC CORE, 3.9nH, -0.3nH/+0.3nH, 0.3A, -55DEGC/+125DEGC, 0402, SMD; ALT_SYMBOLS: INDC1005X60C2L,INDC1005X60C2M; Additional Datasheet URL: https://search.murata.co.jp/Ceramy/image/img/P02/JELF243B-0010.pdf; Budgetary Price: 0.031 EUR; Country of Origin: Japan,Singapore; Datasheet URL: https://www.murata.com/~/media/webrenewal/support/library/catalog/products/inductor/chip/o05e.ashx?la=en-gb; FPLIST: INDC1005X60C2N,INDC1005X60D2N; Frequency: 6GHz; Lead Time: 9; Mass: 0.001g; Maximum Operating Temperature: +125DEGC; Maximum Tolerance: +0.3nH; Minimum Operating Temperature: -55DEGC; Minimum Tolerance: -0.3nH; Mounting Type: SMD; NOTEfied URL: https://notefied-dynamic-precision.com/NOTEfiedWebInterface/part/show?partNumber=03-06630; PCB Package: 0402; Packing Size: 10000; Packing Type: Tape & Reel; Part Number: 03-06630; Part Type: Inductor|RF|CHIP|0402; REACH/SVHC Compliance: Compliant; REACH/SVHC Details: SVHC List Version Jul 7, 2017; REACH/SVHC Source: REACH Declaration; REACH/SVHC Status: Unaffected; ROHS: Compliant; Resistance: 0.18; Revision: R017; Status: Released; Texas Part Status: Under Review; Type: Inductor; Vendor: MURATA; Vendor Part Number: LQG15HS3N9S02D; Vendor Part Status: Active
L32 = INDUCTOR_HOR_1_2: INDUCTOR, RF, CHIP, NON-MAGNETIC CORE, 22nH, -5%/+5%, 0.3A, -55DEGC/+125DEGC, 0402, SMD; Additional Datasheet URL: https://search.murata.co.jp/Ceramy/image/img/P02/JELF243B-0010.pdf; Budgetary Price: 0.03 EUR; Country of Origin: Japan,Singapore; Datasheet URL: https://www.murata.com/~/media/webrenewal/support/library/catalog/products/inductor/chip/o05e.ashx?la=en-gb; Exclusive for Customers: TEXAS INSTRUMENTS NORWAY; Frequency: 1900MHz; Lead Time: 9; Mass: 0.001g; Maximum Operating Temperature: +125DEGC; Maximum Tolerance: +5%; Minimum Operating Temperature: -55DEGC; Minimum Tolerance: -5%; Mounting Type: SMD; NOTEfied URL: https://notefied-dynamic-precision.com/NOTEfiedWebInterface/part/show?partNumber=03-07529; Notes: Standard item: Duplicate Reason: custom footprint for TEXAS INSTRUMENTS NORWAY.; PCB Package: 0402; Packing Size: 10000; Packing Type: Tape & Reel; Part Number: 03-07529; Part Type: Inductor|RF|CHIP|0402; REACH/SVHC Compliance: Compliant; REACH/SVHC Details: SVHC List Version Jul 7, 2017; REACH/SVHC Source: REACH Declaration; REACH/SVHC Status: Unaffected; ROHS: Compliant; Revision: R017; Status: Released; Texas Part Status: Under Review; Type: Inductor; Vendor: MURATA; Vendor Part Number: LQG15HS22NJ02D; Vendor Part Status: Active
